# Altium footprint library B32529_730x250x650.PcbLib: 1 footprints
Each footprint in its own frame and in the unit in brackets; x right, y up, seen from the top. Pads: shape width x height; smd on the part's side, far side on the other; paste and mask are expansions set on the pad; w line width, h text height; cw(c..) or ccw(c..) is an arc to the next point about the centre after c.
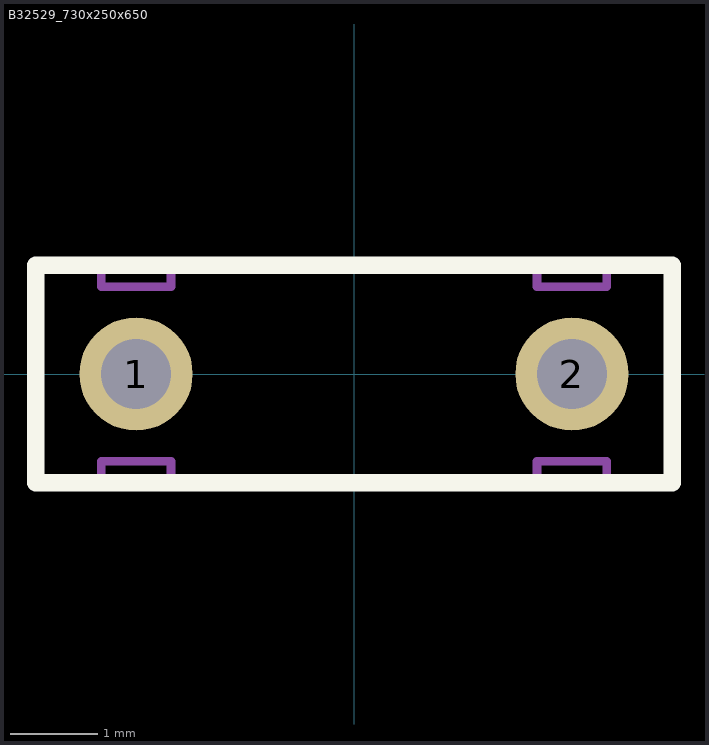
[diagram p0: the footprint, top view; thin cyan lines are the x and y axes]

## B32529_730x250x650 [mm] "TH, 2-Leads, Body 7.3x2.5mm"
height 6.5
pads (2):
  round 1.3 hole 0.8: 1(-2.5,0) 2(2.5,0)
Top Overlay:
  lines w0.2: -3.65,-1.25 3.65,-1.25 3.65,1.25 -3.65,1.25 -3.65,-1.25
Mechanical 5:
  lines w0.1: -2.9,-1.25 -2.9,-1 -2.1,-1 -2.1,-1.25 ; -2.9,1.25 -2.9,1 -2.1,1 -2.1,1.25 ; 2.1,-1.25 2.1,-1 2.9,-1 2.9,-1.25 ; 2.1,1.25 2.1,1 2.9,1 2.9,1.25 ; -3.65,-1.25 -3.65,1.25 3.65,1.25 3.65,-1.25 -3.65,-1.25
  text ".Designator" at -1.524,-0.508 h1.02
3D body: height 1.5, standoff -2.5, extent 2.252,-0.249 2.75,0.25
3D body: height 1.5, standoff -2.5, extent -2.748,-0.249 -2.25,0.25
3D body: height 0.5, standoff 0, extent 2.1,1 2.9,1.25
3D body: height 0.5, standoff 0, extent -2.9,-1.25 -2.1,-1
3D body: height 0.5, standoff 0, extent 2.1,-1.25 2.9,-1
3D body: height 0.5, standoff 0, extent -2.9,1 -2.1,1.25
3D body: height 6.5, standoff 0.5, extent -3.65,-1.25 3.65,1.25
